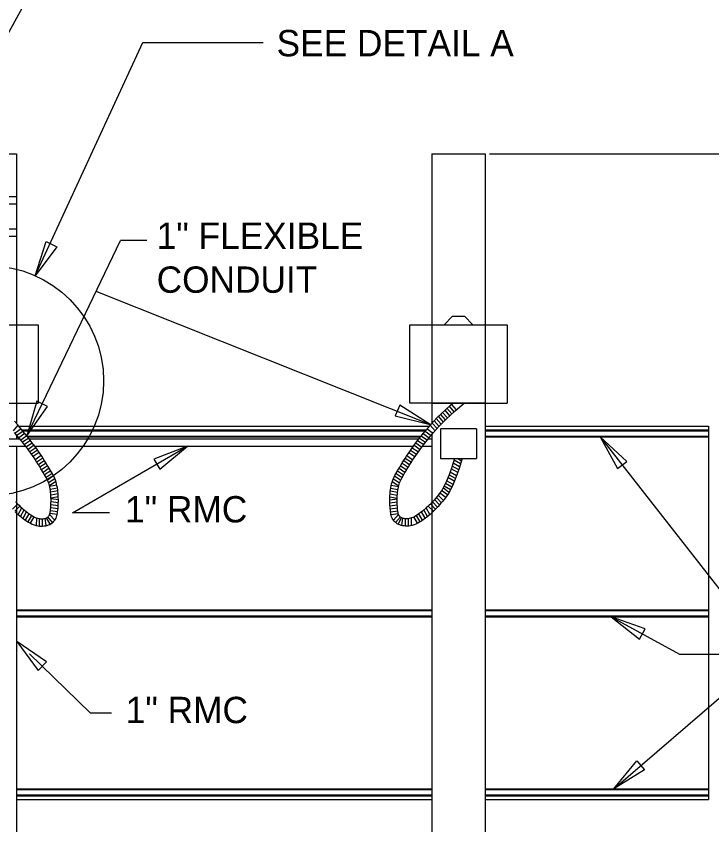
# Model space of a CAD drawing. Extents: x 1299104.6 to 1299141.5, y 239713.3 to 239735.3.
# Drawn here: x 1299124.184 to 1299127.35, y 239729.171 to 239732.853 of the extents above; entities that cross this region are included whole.
import ezdxf

# ---------------------------------------------------------------- set-up
doc = ezdxf.new("R2010")
doc.units = 0
doc.layers.add('DIM TXT', color=7, linetype='Continuous')
doc.layers.add('PTEXT', color=7, linetype='Continuous')

msp = doc.modelspace()

# ---------------------------------------------------------------- linework, layer by layer
at = {"layer": 'DIM TXT'}
for p, q in [((1299124.5411, 239733.4944), (1299123.8182, 239732.1737)), ((1299124.2708, 239731.6711), (1299124.7613, 239732.7324)), ((1299124.7613, 239732.7324), (1299125.3089, 239732.7324)), ((1299126.3377, 239732.2253), (1299127.8349, 239732.2253)), ((1299124.233, 239730.9418), (1299124.6588, 239731.8319)), ((1299124.7795, 239731.8319), (1299124.6588, 239731.8319)), ((1299126.0707, 239730.9929), (1299124.5476, 239731.5996)), ((1299126.842, 239730.9368), (1299127.6142, 239729.9477)), ((1299124.4401, 239730.5915), (1299124.9635, 239730.8953)), ((1299124.6097, 239730.5915), (1299124.4401, 239730.5915)), ((1299126.892, 239730.1183), (1299127.2029, 239729.9477)), ((1299124.2454, 239729.9498), (1299124.5209, 239729.6807)), ((1299126.9033, 239729.3356), (1299127.6142, 239729.9477)), ((1299127.2029, 239729.9477), (1299127.8313, 239729.9477)), ((1299124.5209, 239729.6807), (1299124.6182, 239729.6807))]:
    msp.add_line(p, q, dxfattribs=at)
for points in [[(1299124.3211, 239731.8275), (1299124.3691, 239731.8027), (1299124.2708, 239731.6711)], [(1299124.3272, 239731.0763), (1299124.2785, 239731.0996), (1299124.2331, 239730.9417)], [(1299125.9296, 239731.0821), (1299125.9084, 239731.0324), (1299126.068, 239730.9936)], [(1299126.9204, 239730.7926), (1299126.963, 239730.8258), (1299126.842, 239730.9368)], [(1299124.8102, 239730.8364), (1299124.8376, 239730.7898), (1299124.9635, 239730.8953)], [(1299124.2844, 239729.8739), (1299124.3222, 239729.9125), (1299124.1874, 239730.0064)], [(1299127.0085, 239729.4617), (1299127.0437, 239729.4208), (1299126.9033, 239729.3356)]]:
    msp.add_lwpolyline(points, close=True, dxfattribs=at)
at = {"layer": 'PTEXT'}
for p, q in [((1299123.9424, 239732.2253), (1299124.1854, 239732.2253)), ((1299124.1854, 239732.2253), (1299124.1854, 239730.9982)), ((1299126.0755, 239732.2253), (1299126.3185, 239732.2253)), ((1299126.0755, 239732.2253), (1299126.0755, 239730.9982)), ((1299126.3185, 239732.2253), (1299126.3185, 239726.5336)), ((1299123.9179, 239732.0319), (1299124.1854, 239732.0319)), ((1299123.9179, 239731.9979), (1299124.1854, 239731.9979)), ((1299123.9179, 239731.8845), (1299124.1854, 239731.8845)), ((1299123.9179, 239731.8505), (1299124.1854, 239731.8505)), ((1299124.1854, 239731.4475), (1299124.2851, 239731.4475)), ((1299124.2851, 239731.4475), (1299124.2851, 239731.0909)), ((1299125.9758, 239731.4475), (1299126.4182, 239731.4475)), ((1299125.9758, 239731.0909), (1299125.9758, 239731.4475)), ((1299126.4182, 239731.4475), (1299126.4182, 239731.0909)), ((1299124.1854, 239731.0909), (1299124.2851, 239731.0909)), ((1299126.0755, 239731.0909), (1299125.9758, 239731.0909)), ((1299126.0755, 239731.0909), (1299126.3185, 239731.0909)), ((1299126.3185, 239731.0909), (1299126.4182, 239731.0909)), ((1299126.1347, 239731.0582), (1299126.1564, 239731.0329)), ((1299126.1447, 239731.0673), (1299126.1664, 239731.042)), ((1299126.1546, 239731.0765), (1299126.1764, 239731.0511)), ((1299126.1648, 239731.0853), (1299126.1865, 239731.06)), ((1299126.0961, 239731.0203), (1299126.1179, 239730.9949)), ((1299126.1056, 239731.03), (1299126.1273, 239731.0046)), ((1299126.1151, 239731.0396), (1299126.1369, 239731.0142)), ((1299126.1249, 239731.0489), (1299126.1466, 239731.0236)), ((1299124.1925, 239730.9903), (1299124.1705, 239730.9647)), ((1299124.1956, 239730.9867), (1299126.0654, 239730.9867)), ((1299126.0685, 239730.9903), (1299126.0904, 239730.9647)), ((1299126.0775, 239731.0004), (1299126.0994, 239730.975)), ((1299126.0867, 239731.0105), (1299126.1085, 239730.9851)), ((1299126.3185, 239730.9867), (1299127.3346, 239730.9867)), ((1299127.3346, 239730.9867), (1299127.3346, 239729.2857)), ((1299124.2071, 239730.9732), (1299124.1794, 239730.9545)), ((1299124.1854, 239730.9473), (1299124.1854, 239730.9291)), ((1299124.2158, 239730.9628), (1299124.1881, 239730.9441)), ((1299124.2245, 239730.9523), (1299124.1967, 239730.9336)), ((1299124.233, 239730.9418), (1299124.2053, 239730.9231)), ((1299124.2107, 239730.9689), (1299126.0502, 239730.9689)), ((1299124.2139, 239730.9651), (1299126.047, 239730.9651)), ((1299124.2335, 239730.9412), (1299126.0274, 239730.9412)), ((1299126.0279, 239730.9418), (1299126.0556, 239730.9231)), ((1299126.0365, 239730.9523), (1299126.0642, 239730.9336)), ((1299126.0451, 239730.9628), (1299126.0728, 239730.9441)), ((1299126.0538, 239730.9732), (1299126.0816, 239730.9545)), ((1299126.0755, 239730.9473), (1299126.0755, 239726.5336)), ((1299126.1151, 239730.9738), (1299126.1151, 239730.8383)), ((1299126.2789, 239730.9738), (1299126.1151, 239730.9738)), ((1299126.2789, 239730.9738), (1299126.2789, 239730.8383)), ((1299126.3185, 239730.9689), (1299127.3346, 239730.9689)), ((1299126.3185, 239730.9651), (1299127.3346, 239730.9651)), ((1299126.3185, 239730.9412), (1299127.3346, 239730.9412)), ((1299124.1459, 239730.9291), (1299124.2004, 239730.9291)), ((1299124.1854, 239730.9359), (1299124.1948, 239730.9359)), ((1299124.2415, 239730.9313), (1299124.2137, 239730.9125)), ((1299124.2498, 239730.9205), (1299124.2221, 239730.9019)), ((1299124.258, 239730.9098), (1299124.2304, 239730.8912)), ((1299124.237, 239730.9368), (1299126.024, 239730.9368)), ((1299124.2431, 239730.9291), (1299126.0178, 239730.9291)), ((1299126.0029, 239730.9098), (1299126.0306, 239730.8912)), ((1299126.0111, 239730.9205), (1299126.0388, 239730.9019)), ((1299126.0194, 239730.9313), (1299126.0472, 239730.9125)), ((1299126.0605, 239730.9291), (1299126.0755, 239730.9291)), ((1299126.3185, 239730.9368), (1299127.3346, 239730.9368)), ((1299124.1459, 239730.8953), (1299124.2272, 239730.8953)), ((1299124.1854, 239730.8953), (1299124.1854, 239728.3923)), ((1299124.2661, 239730.899), (1299124.2385, 239730.8803)), ((1299124.274, 239730.8881), (1299124.2464, 239730.8694)), ((1299124.2818, 239730.877), (1299124.2542, 239730.8584)), ((1299124.2688, 239730.8953), (1299125.9921, 239730.8953)), ((1299125.9791, 239730.877), (1299126.0067, 239730.8584)), ((1299125.9869, 239730.8881), (1299126.0145, 239730.8694)), ((1299125.9948, 239730.899), (1299126.0225, 239730.8803)), ((1299126.0337, 239730.8953), (1299126.0755, 239730.8953)), ((1299124.2895, 239730.8659), (1299124.2618, 239730.8473)), ((1299124.2987, 239730.852), (1299124.2711, 239730.8333)), ((1299124.306, 239730.8406), (1299124.2784, 239730.822)), ((1299125.9549, 239730.8406), (1299125.9826, 239730.822)), ((1299125.9622, 239730.852), (1299125.9899, 239730.8333)), ((1299125.9715, 239730.8659), (1299125.9991, 239730.8473)), ((1299126.1151, 239730.8383), (1299126.2789, 239730.8383)), ((1299126.2066, 239730.814), (1299126.177, 239730.8307)), ((1299126.2109, 239730.8271), (1299126.1909, 239730.8383)), ((1299124.3131, 239730.8292), (1299124.2855, 239730.8105)), ((1299124.3202, 239730.8176), (1299124.2926, 239730.799)), ((1299124.3272, 239730.8061), (1299124.2991, 239730.7871)), ((1299124.3343, 239730.7945), (1299124.3065, 239730.7758)), ((1299125.9267, 239730.7945), (1299125.9544, 239730.7758)), ((1299125.9337, 239730.8061), (1299125.9618, 239730.7871)), ((1299125.9407, 239730.8176), (1299125.9683, 239730.799)), ((1299125.9478, 239730.8292), (1299125.9754, 239730.8105)), ((1299126.198, 239730.7874), (1299126.1684, 239730.804)), ((1299126.2023, 239730.8005), (1299126.1727, 239730.8172)), ((1299124.3418, 239730.7834), (1299124.3135, 239730.7642)), ((1299124.348, 239730.7712), (1299124.3203, 239730.7525)), ((1299124.3544, 239730.7593), (1299124.3266, 239730.7405)), ((1299125.9065, 239730.7593), (1299125.9343, 239730.7405)), ((1299125.913, 239730.7712), (1299125.9406, 239730.7525)), ((1299125.9191, 239730.7834), (1299125.9474, 239730.7642)), ((1299126.1834, 239730.7477), (1299126.1554, 239730.7635)), ((1299126.1882, 239730.7605), (1299126.1588, 239730.7771)), ((1299126.1933, 239730.7745), (1299126.1639, 239730.7911)), ((1299124.3602, 239730.7469), (1299124.332, 239730.7279)), ((1299124.3651, 239730.7339), (1299124.3361, 239730.7143)), ((1299125.8958, 239730.7339), (1299125.9249, 239730.7143)), ((1299125.9007, 239730.7469), (1299125.929, 239730.7279)), ((1299126.1665, 239730.709), (1299126.1374, 239730.7254)), ((1299126.1723, 239730.7212), (1299126.1432, 239730.7376)), ((1299126.1778, 239730.7354), (1299126.1488, 239730.7517)), ((1299124.3695, 239730.7177), (1299124.3367, 239730.7116)), ((1299124.372, 239730.7044), (1299124.3393, 239730.6984)), ((1299124.3739, 239730.691), (1299124.3411, 239730.685)), ((1299125.887, 239730.691), (1299125.9198, 239730.685)), ((1299125.8889, 239730.7044), (1299125.9216, 239730.6984)), ((1299125.8914, 239730.7177), (1299125.9242, 239730.7116)), ((1299126.1466, 239730.6729), (1299126.1199, 239730.693)), ((1299126.1537, 239730.6844), (1299126.1268, 239730.7047)), ((1299126.1606, 239730.6968), (1299126.1315, 239730.7132)), ((1299124.3752, 239730.6775), (1299124.3423, 239730.6714)), ((1299124.376, 239730.6639), (1299124.3429, 239730.6578)), ((1299124.3763, 239730.6507), (1299124.3429, 239730.6553)), ((1299125.8846, 239730.6507), (1299125.918, 239730.6553)), ((1299125.8849, 239730.6639), (1299125.918, 239730.6578)), ((1299125.8857, 239730.6775), (1299125.9187, 239730.6714)), ((1299126.1109, 239730.6275), (1299126.0877, 239730.6515)), ((1299126.1198, 239730.6377), (1299126.0965, 239730.6618)), ((1299126.1286, 239730.6481), (1299126.1052, 239730.6722)), ((1299126.1391, 239730.6616), (1299126.1125, 239730.6817)), ((1299124.1684, 239730.608), (1299124.1915, 239730.6319)), ((1299124.1781, 239730.5986), (1299124.2012, 239730.6225)), ((1299124.194, 239730.5842), (1299124.2108, 239730.6138)), ((1299124.3746, 239730.61), (1299124.3416, 239730.6146)), ((1299124.3756, 239730.6235), (1299124.3425, 239730.6281)), ((1299124.3762, 239730.6371), (1299124.343, 239730.6417)), ((1299125.8848, 239730.6371), (1299125.918, 239730.6417)), ((1299125.8853, 239730.6235), (1299125.9184, 239730.6281)), ((1299125.8863, 239730.61), (1299125.9193, 239730.6146)), ((1299126.067, 239730.5842), (1299126.0501, 239730.6138)), ((1299126.0829, 239730.5986), (1299126.0597, 239730.6225)), ((1299126.0926, 239730.608), (1299126.0694, 239730.6319)), ((1299126.1019, 239730.6177), (1299126.0787, 239730.6417)), ((1299124.2044, 239730.5753), (1299124.2212, 239730.6047)), ((1299124.2156, 239730.5677), (1299124.2321, 239730.5966)), ((1299124.2272, 239730.5579), (1299124.2438, 239730.5869)), ((1299124.2385, 239730.5504), (1299124.255, 239730.5794)), ((1299124.2503, 239730.5438), (1299124.2668, 239730.5728)), ((1299124.3502, 239730.5482), (1299124.3283, 239730.5733)), ((1299124.3599, 239730.5576), (1299124.3366, 239730.5843)), ((1299124.3708, 239730.5833), (1299124.3377, 239730.5879)), ((1299124.3731, 239730.5966), (1299124.3401, 239730.6012)), ((1299125.8878, 239730.5966), (1299125.9208, 239730.6012)), ((1299125.8901, 239730.5833), (1299125.9232, 239730.5879)), ((1299125.901, 239730.5576), (1299125.9243, 239730.5843)), ((1299125.9107, 239730.5482), (1299125.9326, 239730.5733)), ((1299126.0106, 239730.5438), (1299125.9941, 239730.5728)), ((1299126.0224, 239730.5504), (1299126.0059, 239730.5794)), ((1299126.0337, 239730.5579), (1299126.0172, 239730.5869)), ((1299126.0453, 239730.5677), (1299126.0288, 239730.5966)), ((1299126.0565, 239730.5753), (1299126.0398, 239730.6047)), ((1299124.2774, 239730.5337), (1299124.2777, 239730.5682)), ((1299124.2909, 239730.5314), (1299124.2912, 239730.565)), ((1299124.3044, 239730.5311), (1299124.3047, 239730.5645)), ((1299124.3213, 239730.5335), (1299124.3169, 239730.5668)), ((1299124.3384, 239730.5398), (1299124.3226, 239730.5692)), ((1299125.9225, 239730.5398), (1299125.9383, 239730.5692)), ((1299125.9396, 239730.5335), (1299125.9441, 239730.5668)), ((1299125.9565, 239730.5311), (1299125.9563, 239730.5645)), ((1299125.97, 239730.5314), (1299125.9698, 239730.565)), ((1299125.9835, 239730.5337), (1299125.9832, 239730.5682)), ((1299124.1854, 239730.1504), (1299126.0755, 239730.1504)), ((1299124.1854, 239730.1461), (1299126.0755, 239730.1461)), ((1299126.3185, 239730.1504), (1299127.3346, 239730.1504)), ((1299126.3185, 239730.1461), (1299127.3346, 239730.1461)), ((1299124.1854, 239730.1221), (1299126.0755, 239730.1221)), ((1299124.1854, 239730.1183), (1299126.0755, 239730.1183)), ((1299126.3185, 239730.1221), (1299127.3346, 239730.1221)), ((1299126.3185, 239730.1183), (1299127.3346, 239730.1183)), ((1299124.1854, 239729.3356), (1299126.0755, 239729.3356)), ((1299124.1854, 239729.3313), (1299126.0755, 239729.3313)), ((1299126.3185, 239729.3356), (1299127.3346, 239729.3356)), ((1299126.3185, 239729.3313), (1299127.3346, 239729.3313)), ((1299124.1854, 239729.3073), (1299126.0755, 239729.3073)), ((1299124.1854, 239729.3035), (1299126.0755, 239729.3035)), ((1299124.1854, 239729.2857), (1299126.0755, 239729.2857)), ((1299126.3185, 239729.3073), (1299127.3346, 239729.3073)), ((1299126.3185, 239729.3035), (1299127.3346, 239729.3035)), ((1299126.3185, 239729.2857), (1299127.3346, 239729.2857))]:
    msp.add_line(p, q, dxfattribs=at)
for points in [[(1299126.1315, 239731.4475), (1299126.1693, 239731.4865), (1299126.2247, 239731.4865), (1299126.2625, 239731.4475)], [(1299123.9424, 239731.4475), (1299124.1854, 239731.4475)], [(1299123.9424, 239731.0909), (1299124.1854, 239731.0909)], [(1299126.2145, 239730.8383), (1299126.1986, 239730.789), (1299126.1853, 239730.7525), (1299126.173, 239730.7227), (1299126.1616, 239730.6988), (1299126.1511, 239730.6797), (1299126.1413, 239730.6647), (1299126.1323, 239730.6527), (1299126.1244, 239730.6431), (1299126.1173, 239730.6348), (1299126.1107, 239730.6273), (1299126.1045, 239730.6205), (1299126.0986, 239730.6141), (1299126.0927, 239730.6081), (1299126.0868, 239730.6023), (1299126.0807, 239730.5965), (1299126.0743, 239730.5907), (1299126.0675, 239730.5846), (1299126.0602, 239730.5784), (1299126.0526, 239730.5721), (1299126.0447, 239730.5659), (1299126.0366, 239730.5599), (1299126.0284, 239730.5542), (1299126.02, 239730.5489), (1299126.0116, 239730.5442), (1299126.0032, 239730.5402), (1299125.9949, 239730.537), (1299125.9867, 239730.5345), (1299125.9788, 239730.5326), (1299125.971, 239730.5315), (1299125.9634, 239730.531), (1299125.9561, 239730.5311), (1299125.9491, 239730.5317), (1299125.9424, 239730.5328), (1299125.9359, 239730.5344), (1299125.9298, 239730.5365), (1299125.9239, 239730.5391), (1299125.9185, 239730.542), (1299125.9134, 239730.5454), (1299125.9087, 239730.5492), (1299125.9045, 239730.5533), (1299125.9008, 239730.5579), (1299125.8976, 239730.5628), (1299125.895, 239730.5679), (1299125.8929, 239730.5733), (1299125.8912, 239730.5788), (1299125.8898, 239730.5845), (1299125.8887, 239730.5905), (1299125.8878, 239730.5967), (1299125.887, 239730.6034), (1299125.8863, 239730.6106), (1299125.8857, 239730.6182), (1299125.8852, 239730.6261), (1299125.8848, 239730.6344), (1299125.8846, 239730.643), (1299125.8846, 239730.6518), (1299125.8848, 239730.6608), (1299125.8852, 239730.6699), (1299125.8858, 239730.679), (1299125.8866, 239730.6882), (1299125.8878, 239730.6972), (1299125.8891, 239730.7062), (1299125.8908, 239730.715), (1299125.8928, 239730.7235), (1299125.8951, 239730.7318), (1299125.8978, 239730.7397), (1299125.9008, 239730.7473), (1299125.9042, 239730.7547), (1299125.9078, 239730.7618), (1299125.9116, 239730.7689), (1299125.9158, 239730.7762), (1299125.9202, 239730.7837), (1299125.9249, 239730.7915), (1299125.93, 239730.7999), (1299125.9354, 239730.8089), (1299125.9412, 239730.8185), (1299125.9473, 239730.8284), (1299125.9538, 239730.8388), (1299125.9606, 239730.8494), (1299125.9676, 239730.8602), (1299125.975, 239730.8712), (1299125.9827, 239730.8822), (1299125.9907, 239730.8934), (1299125.999, 239730.9047), (1299126.0078, 239730.9162), (1299126.0169, 239730.928), (1299126.0265, 239730.9401), (1299126.0367, 239730.9526), (1299126.0473, 239730.9655), (1299126.0587, 239730.979), (1299126.0711, 239730.9933), (1299126.0849, 239731.0085), (1299126.1003, 239731.0248), (1299126.1179, 239731.0423), (1299126.1378, 239731.0611), (1299126.1605, 239731.0816), (1299126.1714, 239731.0909)], [(1299126.1795, 239730.8383), (1299126.1671, 239730.7998), (1299126.1543, 239730.7645), (1299126.1426, 239730.7362), (1299126.132, 239730.7141), (1299126.1225, 239730.6969), (1299126.1139, 239730.6837), (1299126.1062, 239730.6733), (1299126.0989, 239730.6645), (1299126.0921, 239730.6566), (1299126.0858, 239730.6495), (1299126.08, 239730.643), (1299126.0745, 239730.6371), (1299126.0691, 239730.6316), (1299126.0636, 239730.6262), (1299126.058, 239730.6209), (1299126.052, 239730.6154), (1299126.0456, 239730.6097), (1299126.0388, 239730.6039), (1299126.0317, 239730.598), (1299126.0245, 239730.5924), (1299126.0172, 239730.587), (1299126.01, 239730.582), (1299126.003, 239730.5776), (1299125.9963, 239730.5738), (1299125.9899, 239730.5708), (1299125.9839, 239730.5684), (1299125.9781, 239730.5667), (1299125.9726, 239730.5654), (1299125.9674, 239730.5646), (1299125.9625, 239730.5643), (1299125.9578, 239730.5643), (1299125.9534, 239730.5647), (1299125.9492, 239730.5654), (1299125.9453, 239730.5664), (1299125.9418, 239730.5676), (1299125.9385, 239730.569), (1299125.9356, 239730.5706), (1299125.9331, 239730.5723), (1299125.9309, 239730.574), (1299125.9292, 239730.5758), (1299125.9277, 239730.5776), (1299125.9265, 239730.5795), (1299125.9254, 239730.5816), (1299125.9243, 239730.5843), (1299125.9233, 239730.5875), (1299125.9224, 239730.5913), (1299125.9216, 239730.5959), (1299125.9208, 239730.6012), (1299125.9201, 239730.6071), (1299125.9194, 239730.6136), (1299125.9189, 239730.6205), (1299125.9184, 239730.6279), (1299125.9181, 239730.6355), (1299125.9179, 239730.6434), (1299125.9179, 239730.6515), (1299125.9181, 239730.6598), (1299125.9184, 239730.668), (1299125.919, 239730.6763), (1299125.9198, 239730.6846), (1299125.9207, 239730.6926), (1299125.922, 239730.7005), (1299125.9234, 239730.7081), (1299125.9251, 239730.7152), (1299125.927, 239730.722), (1299125.9291, 239730.7283), (1299125.9315, 239730.7343), (1299125.9342, 239730.7403), (1299125.9373, 239730.7464), (1299125.9407, 239730.7527), (1299125.9446, 239730.7594), (1299125.9488, 239730.7666), (1299125.9535, 239730.7744), (1299125.9585, 239730.7828), (1299125.9639, 239730.7917), (1299125.9696, 239730.8011), (1299125.9756, 239730.8109), (1299125.9819, 239730.821), (1299125.9885, 239730.8313), (1299125.9954, 239730.8418), (1299126.0025, 239730.8524), (1299126.0099, 239730.863), (1299126.0176, 239730.8738), (1299126.0257, 239730.8848), (1299126.0342, 239730.8959), (1299126.0431, 239730.9074), (1299126.0525, 239730.9192), (1299126.0624, 239730.9315), (1299126.0729, 239730.9442), (1299126.084, 239730.9574), (1299126.096, 239730.9712), (1299126.1093, 239730.9859), (1299126.1242, 239731.0015), (1299126.1411, 239731.0184), (1299126.1604, 239731.0367), (1299126.1825, 239731.0565), (1299126.2226, 239731.0909)], [(1299126.3185, 239731.0909), (1299125.9758, 239731.0909)], [(1299124.1803, 239730.5965), (1299124.1866, 239730.5907), (1299124.1935, 239730.5846), (1299124.2007, 239730.5784), (1299124.2083, 239730.5721), (1299124.2162, 239730.5659), (1299124.2243, 239730.5599), (1299124.2325, 239730.5542), (1299124.2409, 239730.5489), (1299124.2493, 239730.5442), (1299124.2577, 239730.5402), (1299124.266, 239730.537), (1299124.2742, 239730.5345), (1299124.2822, 239730.5326), (1299124.2899, 239730.5315), (1299124.2975, 239730.531), (1299124.3048, 239730.5311), (1299124.3118, 239730.5317), (1299124.3186, 239730.5328), (1299124.325, 239730.5344), (1299124.3312, 239730.5365), (1299124.337, 239730.5391), (1299124.3424, 239730.542), (1299124.3475, 239730.5454), (1299124.3522, 239730.5492), (1299124.3564, 239730.5533), (1299124.3601, 239730.5579), (1299124.3633, 239730.5628), (1299124.366, 239730.5679), (1299124.3681, 239730.5733), (1299124.3697, 239730.5788), (1299124.3711, 239730.5845), (1299124.3722, 239730.5905), (1299124.3731, 239730.5967), (1299124.3739, 239730.6034), (1299124.3747, 239730.6106), (1299124.3753, 239730.6182), (1299124.3758, 239730.6261), (1299124.3761, 239730.6344), (1299124.3763, 239730.643), (1299124.3763, 239730.6518), (1299124.3761, 239730.6608), (1299124.3757, 239730.6699), (1299124.3751, 239730.679), (1299124.3743, 239730.6882), (1299124.3732, 239730.6972), (1299124.3718, 239730.7062), (1299124.3701, 239730.715), (1299124.3681, 239730.7235), (1299124.3658, 239730.7318), (1299124.3631, 239730.7397), (1299124.3601, 239730.7473), (1299124.3568, 239730.7547), (1299124.3532, 239730.7618), (1299124.3493, 239730.7689), (1299124.3451, 239730.7762), (1299124.3407, 239730.7837), (1299124.336, 239730.7915), (1299124.3309, 239730.7999), (1299124.3255, 239730.8089), (1299124.3197, 239730.8185), (1299124.3136, 239730.8284), (1299124.3071, 239730.8388), (1299124.3004, 239730.8494), (1299124.2933, 239730.8602), (1299124.2859, 239730.8712), (1299124.2782, 239730.8822), (1299124.2702, 239730.8934), (1299124.2619, 239730.9047), (1299124.2531, 239730.9162), (1299124.244, 239730.928), (1299124.2344, 239730.9401), (1299124.2243, 239730.9526), (1299124.2136, 239730.9655), (1299124.2022, 239730.979), (1299124.1898, 239730.9933), (1299124.1761, 239731.0085)], [(1299124.1809, 239730.643), (1299124.1864, 239730.6371), (1299124.1918, 239730.6316), (1299124.1973, 239730.6262), (1299124.2029, 239730.6209), (1299124.2089, 239730.6154), (1299124.2154, 239730.6097), (1299124.2222, 239730.6039), (1299124.2292, 239730.598), (1299124.2364, 239730.5924), (1299124.2437, 239730.587), (1299124.2509, 239730.582), (1299124.2579, 239730.5776), (1299124.2646, 239730.5738), (1299124.271, 239730.5708), (1299124.277, 239730.5684), (1299124.2828, 239730.5667), (1299124.2883, 239730.5654), (1299124.2935, 239730.5646), (1299124.2984, 239730.5643), (1299124.3031, 239730.5643), (1299124.3076, 239730.5647), (1299124.3117, 239730.5654), (1299124.3156, 239730.5664), (1299124.3192, 239730.5676), (1299124.3224, 239730.569), (1299124.3253, 239730.5706), (1299124.3278, 239730.5723), (1299124.33, 239730.574), (1299124.3318, 239730.5758), (1299124.3332, 239730.5776), (1299124.3345, 239730.5795), (1299124.3356, 239730.5816), (1299124.3366, 239730.5843), (1299124.3376, 239730.5875), (1299124.3385, 239730.5913), (1299124.3393, 239730.5959), (1299124.3401, 239730.6012), (1299124.3408, 239730.6071), (1299124.3415, 239730.6136), (1299124.3421, 239730.6205), (1299124.3425, 239730.6279), (1299124.3428, 239730.6355), (1299124.343, 239730.6434), (1299124.343, 239730.6515), (1299124.3428, 239730.6598), (1299124.3425, 239730.668), (1299124.3419, 239730.6763), (1299124.3412, 239730.6846), (1299124.3402, 239730.6926), (1299124.339, 239730.7005), (1299124.3375, 239730.7081), (1299124.3358, 239730.7152), (1299124.334, 239730.722), (1299124.3318, 239730.7283), (1299124.3294, 239730.7343), (1299124.3267, 239730.7403), (1299124.3237, 239730.7464), (1299124.3202, 239730.7527), (1299124.3164, 239730.7594), (1299124.3121, 239730.7666), (1299124.3074, 239730.7744), (1299124.3024, 239730.7828), (1299124.297, 239730.7917), (1299124.2913, 239730.8011), (1299124.2853, 239730.8109), (1299124.279, 239730.821), (1299124.2724, 239730.8313), (1299124.2655, 239730.8418), (1299124.2584, 239730.8524), (1299124.251, 239730.863), (1299124.2433, 239730.8738), (1299124.2352, 239730.8848), (1299124.2267, 239730.8959), (1299124.2178, 239730.9074), (1299124.2084, 239730.9192), (1299124.1985, 239730.9315), (1299124.188, 239730.9442), (1299124.1769, 239730.9574)]]:
    msp.add_lwpolyline(points, dxfattribs=at)
msp.add_lwpolyline([(1299127.0211, 239730.0167), (1299127.0471, 239730.0641), (1299126.892, 239730.1183)], close=True, dxfattribs=at)
msp.add_circle((1299124.0586, 239731.1925), 0.5236, dxfattribs=at)

# ---------------------------------------------------------------- texts
at = {"layer": 'DIM TXT'}
for s, p in [('SEE DETAIL A', (1299125.3694, 239732.67)), ('1" FLEXIBLE ', (1299124.8236, 239731.7933)), ('CONDUIT', (1299124.8236, 239731.5933)), ('1" RMC', (1299124.6797, 239730.5477)), ('1" RMC', (1299124.6828, 239729.6339))]:
    msp.add_text(s, height=0.12, dxfattribs=at).set_placement(p)

doc.saveas('drawing.dxf')
